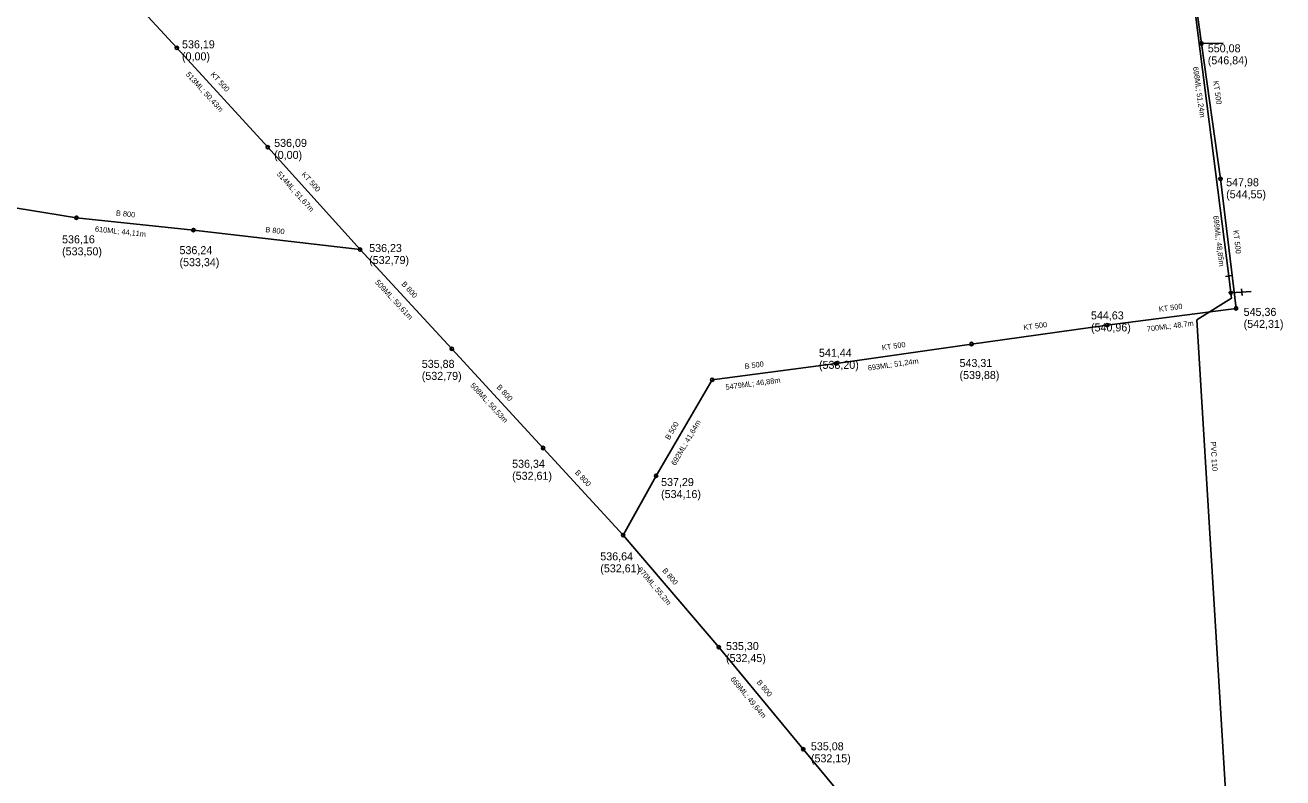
# Model space of a CAD drawing. Extents: x -867696 to -865033, y -1042522 to -1039817.
# Drawn here: x -867376.4 to -866905, y -1040504.6 to -1040222.5 of the extents above; entities that cross this region are included whole.
import ezdxf

# ---------------------------------------------------------------- set-up
doc = ezdxf.new("R2010")
doc.units = 0
for name, color, linetype in [('KN - jednotna', 7, 'Continuous'), ('KN - popis material', 7, 'Continuous'), ('KN - popis ostatni', 7, 'Continuous'), ('KN - popis usek delka', 7, 'Continuous'), ('KN - pripojka', 7, 'Continuous'), ('KN - sachta komora', 7, 'Continuous'), ('Level 1', 7, 'Continuous'), ('V - armatura', 7, 'Continuous'), ('V - hydrant', 7, 'Continuous'), ('V - ostatni', 7, 'Continuous'), ('V - popis material', 7, 'Continuous'), ('V - pripojka', 7, 'Continuous'), ('V - rozvadeci', 7, 'Continuous')]:
    doc.layers.add(name, color=color, linetype=linetype)

# ---------------------------------------------------------------- blocks, each defined once
blk = doc.blocks.new('100.M')
at = {"layer": 'Level 1'}
blk.add_circle((0, 0), 1.27, dxfattribs=at)
blk = doc.blocks.new('147')
at = {"layer": 'Level 1'}
blk.add_line((0, 1.27), (0, -1.27), dxfattribs=at)
blk = doc.blocks.new('111')
at = {"layer": 'Level 1'}
for p, q in [((0.42, 0.72), (-0.83, 0)), ((-0.83, 0), (0.42, -0.72)), ((0.42, -0.72), (0.42, 0.72))]:
    blk.add_line(p, q, dxfattribs=at)
blk = doc.blocks.new('150')
at = {"layer": 'Level 1'}
blk.add_line((0, 1.27), (0, -1.27), dxfattribs=at)

msp = doc.modelspace()

# ---------------------------------------------------------------- linework, layer by layer
at = {"layer": 'KN - jednotna'}
for points in [[(-867351.948, -1040195.749), (-867319.518, -1040231.057)], [(-866938.241, -1040209.707), (-866935.579, -1040229.396)], [(-867319.518, -1040231.057), (-867285.458, -1040268.247)], [(-866935.579, -1040229.396), (-866928.399, -1040280.129)], [(-867285.458, -1040268.247), (-867250.85, -1040306.61)], [(-866928.399, -1040280.129), (-866922.588, -1040328.628)], [(-867357.159, -1040294.689), (-867402.519, -1040287.289)], [(-867313.29, -1040299.319), (-867357.159, -1040294.689)], [(-867250.85, -1040306.61), (-867313.29, -1040299.319)], [(-867216.466, -1040343.748), (-867250.85, -1040306.61)], [(-866922.588, -1040328.628), (-866970.887, -1040334.898)], [(-866970.887, -1040334.898), (-867021.729, -1040341.998)], [(-867216.466, -1040343.748), (-867182.285, -1040380.959)], [(-867072.446, -1040349.266), (-867021.729, -1040341.998)], [(-867118.917, -1040355.419), (-867072.446, -1040349.266)], [(-867139.929, -1040391.368), (-867118.917, -1040355.419)], [(-867182.285, -1040380.959), (-867152.279, -1040413.648)], [(-867152.279, -1040413.648), (-867139.929, -1040391.368)], [(-867152.279, -1040413.648), (-867116.439, -1040455.629)], [(-867084.758, -1040493.849), (-867116.439, -1040455.629)], [(-867051.86, -1040533.696), (-867084.758, -1040493.849)]]:
    msp.add_lwpolyline(points, dxfattribs=at)
at = {"layer": 'KN - pripojka'}
msp.add_lwpolyline([(-866935.579, -1040229.396), (-866927.46, -1040229.32)], dxfattribs=at)
at = {"layer": 'V - pripojka'}
msp.add_lwpolyline([(-866924.552, -1040322.871), (-866916.877, -1040322.272)], dxfattribs=at)
at = {"layer": 'V - rozvadeci'}
for points in [[(-866957.054, -1040067.457), (-866955.248, -1040081.074), (-866943.379, -1040174.303), (-866925.276, -1040316.515)], [(-866925.276, -1040316.515), (-866924.552, -1040322.871)], [(-866924.552, -1040322.871), (-866924.327, -1040324.846), (-866937.332, -1040332.974), (-866916.288, -1040677.377)]]:
    msp.add_lwpolyline(points, dxfattribs=at)

# ---------------------------------------------------------------- block references
at = {"layer": 'KN - sachta komora'}
for p, xscale, yscale, rotation in [((-867319.518, -1040231.057), 0.50000000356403, 0.50000000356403, 133.00000056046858), ((-866935.579, -1040229.396), 0.49999999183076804, 0.49999999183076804, 98.00000038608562), ((-867285.458, -1040268.247), 0.50000000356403, 0.50000000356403, 133.00000056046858), ((-866928.399, -1040280.129), 0.49999999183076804, 0.49999999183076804, 98.00000038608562), ((-867357.159, -1040294.689), 0.5049058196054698, 0.5049058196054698, 169.38969821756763), ((-867313.29, -1040299.319), 0.5005608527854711, 0.5005608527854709, 173.41739016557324), ((-867250.85, -1040306.61), 0.5069432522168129, 0.5069432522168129, 152.43468640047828), ((-866922.588, -1040328.628), 0.49999999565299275, 0.4999999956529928, -127.00000193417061), ((-866970.887, -1040334.898), 0.5046025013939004, 0.5046025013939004, -168.88308178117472), ((-867021.729, -1040341.998), 0.5041888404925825, 0.5041888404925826, -168.37362119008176), ((-867216.466, -1040343.748), 0.50000000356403, 0.50000000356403, 133.00000056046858), ((-867072.446, -1040349.266), 0.5046025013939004, 0.5046025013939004, 11.116918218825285), ((-867118.917, -1040355.419), 0.4999999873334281, 0.499999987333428, 34.00000045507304), ((-867182.285, -1040380.959), 0.50000000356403, 0.50000000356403, 133.00000056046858), ((-867139.929, -1040391.368), 0.5000000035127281, 0.5000000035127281, 61.000001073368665), ((-867152.279, -1040413.648), 0.5000000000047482, 0.5000000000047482, 132.0000013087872), ((-867116.439, -1040455.629), 0.5000000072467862, 0.5000000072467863, 130.99999910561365), ((-867084.758, -1040493.849), 0.5000000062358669, 0.5000000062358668, 130.0000013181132)]:
    msp.add_blockref('100.M', p, dxfattribs=dict(at, xscale=xscale, yscale=yscale, rotation=rotation))
at = {"layer": 'V - armatura', "xscale": 1.000191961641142, "yscale": 1.000191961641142, "rotation": 97.08900113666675}
msp.add_blockref('147', (-866925.276, -1040316.515), dxfattribs=at)
at = {"layer": 'V - hydrant', "xscale": 1.0018265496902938, "yscale": 1.0018265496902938, "rotation": 6.078126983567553}
msp.add_blockref('150', (-866920.388, -1040322.546), dxfattribs=at)
at = {"layer": 'V - ostatni', "xscale": 1.000191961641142, "yscale": 1.000191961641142, "rotation": 97.08900113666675}
msp.add_blockref('111', (-866924.552, -1040322.871), dxfattribs=at)

# ---------------------------------------------------------------- texts
at = {"layer": 'KN - popis material'}
for s, rotation, p in [('KT 500', 312.48, (-867307.032, -1040241.137)), ('KT 500', 278.06, (-866931.156, -1040243.526)), ('KT 500', 312.05, (-867272.93, -1040278.551)), ('B 800', 353.98, (-867342.411, -1040293.832)), ('B 800', 353.34, (-867286.426, -1040300.04)), ('KT 500', 276.83, (-866923.667, -1040299.444)), ('B 800', 312.79, (-867235.5, -1040319.656)), ('KT 500', 7.4, (-866951.397, -1040329.948)), ('KT 500', 7.95, (-867002.096, -1040336.833)), ('KT 500', 8.16, (-867055.153, -1040344.364)), ('B 500', 7.54, (-867106.619, -1040351.37)), ('B 800', 312.57, (-867199.826, -1040358.315)), ('B 500', 59.69, (-867134.949, -1040378.092)), ('B 800', 312.55, (-867170.468, -1040390.283)), ('B 800', 310.49, (-867137.736, -1040426.987)), ('B 800', 309.66, (-867102.368, -1040468.844))]:
    msp.add_text(s, height=2, rotation=rotation, dxfattribs=at).set_placement(p)
at = {"layer": 'KN - popis ostatni'}
for s, p in [('536,19 ', (-867317.578, -1040231.197)), ('(0,00)', (-867317.578, -1040235.697)), ('550,08 ', (-866933.169, -1040232.686)), ('(546,84)', (-866933.169, -1040237.186)), ('536,09 ', (-867283.048, -1040268.137)), ('(0,00)', (-867283.048, -1040272.637)), ('547,98 ', (-866926.289, -1040282.879)), ('(544,55)', (-866926.289, -1040287.379)), ('536,16 ', (-867362.529, -1040304.259)), ('(533,50)', (-867362.529, -1040308.759)), ('536,24 ', (-867318.52, -1040308.329)), ('536,23 ', (-867247.44, -1040307.53)), ('(533,34)', (-867318.52, -1040312.829)), ('(532,79)', (-867247.44, -1040312.03)), ('544,63 ', (-866976.947, -1040332.778)), ('545,36 ', (-866919.738, -1040331.458)), ('(540,96)', (-866976.947, -1040337.278)), ('(542,31)', (-866919.738, -1040335.958)), ('541,44 ', (-867078.886, -1040346.796)), ('535,88 ', (-867227.726, -1040350.928)), ('(538,20)', (-867078.886, -1040351.296)), ('543,31 ', (-867026.209, -1040350.608)), ('(532,79)', (-867227.726, -1040355.428)), ('(539,88)', (-867026.209, -1040355.108)), ('536,34 ', (-867193.875, -1040388.369)), ('(532,61)', (-867193.875, -1040392.869)), ('537,29 ', (-867138.049, -1040395.218)), ('(534,16)', (-867138.049, -1040399.718)), ('536,64 ', (-867160.829, -1040423.058)), ('(532,61)', (-867160.829, -1040427.558)), ('535,30 ', (-867113.719, -1040456.669)), ('(532,45)', (-867113.719, -1040461.169)), ('535,08 ', (-867081.898, -1040494.229)), ('(532,15)', (-867081.898, -1040498.729))]:
    msp.add_text(s, height=3, dxfattribs=at).set_placement(p)
at = {"layer": 'KN - popis usek delka'}
for s, rotation, p in [('513ML; 50,43m', 312.48, (-867316.301, -1040241.083)), ('698ML; 51,24m', 278.06, (-866938.772, -1040238.241)), ('514ML; 51,67m', 312.05, (-867282.199, -1040278.429)), ('699ML; 48,85m', 276.83, (-866931.168, -1040293.997)), ('610ML; 44,11m', 353.98, (-867350.285, -1040299.84)), ('509ML; 50,61m', 312.79, (-867245.381, -1040318.992)), ('700ML; 48,7m', 7.4, (-866955.877, -1040337.387)), ('693ML; 51,24m', 8.16, (-867060.425, -1040351.989)), ('5479ML; 46,88m', 7.54, (-867113.756, -1040359.174)), ('508ML; 50,53m', 312.57, (-867209.704, -1040357.613)), ('692ML; 41,64m', 59.69, (-867132.713, -1040387.739)), ('670ML; 55,2m', 310.49, (-867146.998, -1040426.612)), ('669ML; 49,64m', 309.66, (-867112.198, -1040467.642))]:
    msp.add_text(s, height=1.99999, rotation=rotation, dxfattribs=at).set_placement(p)
at = {"layer": 'V - popis material'}
msp.add_text('PVC 110', height=2, rotation=273.5, dxfattribs=at).set_placement((-866932.137, -1040378.643))

doc.saveas('drawing.dxf')
